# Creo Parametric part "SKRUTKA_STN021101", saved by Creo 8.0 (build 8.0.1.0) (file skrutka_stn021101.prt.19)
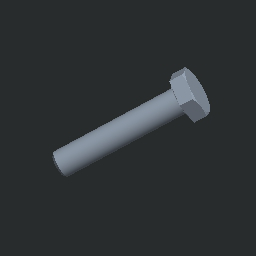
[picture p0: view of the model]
Units: Custom; MM, KILOGRAM, SECS
Materials in the file: OCEL_N

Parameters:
  KATEGORIE = "4"
  NAZOV = "SKRUTKA_STN021101"
  NORMA = "STN 02 1101"
  N2 = "21"
  N3 = "1"
  PTC_MATERIAL_NAME = "OCEL_N"
  PLACEMENT = "A"

Other parameters: HMOTNOST, HUSTOTA, HMOTNOST_1, D42, D2, D7, D25, D30, D1, D41, THREADS_PER_INCH

Created from: STN_021101_SKRUTKA_6HR.PRT

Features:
  1. chamfer
  2. datum plane "DTM1"
  3. protrusion
  4. datum plane "DTM6"
  5. cut
  6. datum plane "DTM7"
  7. cut
  8. datum plane "DTM8"
  9. datum plane "DTM9"

Other named items: S_00046, S_00048, S_00066, S_00073, S_00076, S_00144, S_00151, S_00158, S_00160, S_00162, S_00164, S_00166, S_00168, S_00299, S_00309, S_00360, S_00362, S_00376

Layers: BEZUGSEBENEN, NORMTEILE

Family table entries: SKRUTKA_M3X16, SKRUTKA_STN021101, value(d_val), 2/0, 2/(, value(i_val), SKRUTKA_M3X20, SKRUTKA_STN021101, 2/4, 2/(, SKRUTKA_M3X25, SKRUTKA_STN021101, 2/9, 2/(, SKRUTKA_M4X25, SKRUTKA_STN021101, 2/9, 2/,, SKRUTKA_M4X30, SKRUTKA_STN021101, 2/>, 2/,, SKRUTKA_M4X35, SKRUTKA_STN021101, 2/,, SKRUTKA_M4X40, SKRUTKA_STN021101, 2/D, 2/,, SKRUTKA_M5X25, SKRUTKA_STN021101, 2/9, 2/ , 2/0, SKRUTKA_M5X30, SKRUTKA_STN021101, 2/>, 2/ , 2/0, SKRUTKA_M5X35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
